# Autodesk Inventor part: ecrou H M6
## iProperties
Author: chr
Created: 2001-06
Part Number: ecrou H M6
Material: Par défaut
Document SubType Name: Modélisation
Designer: chr
Control State: 0
Master: False
Checked Out: False
PropertySet Name: Design Tracking Control
Shininess: 20.0
PropertySet Name: _Private Model Information
Length Units: 11269
Angle Units: 11286
Time Units: 11279
Mass Units: 11290
Length Display Precision: 3
Angle Display Precision: 2
Compacted: False
Density: 0.0
Volumn: 0.0
Area: 0.0
PropertySet Name: Model Information
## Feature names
1. Base1
